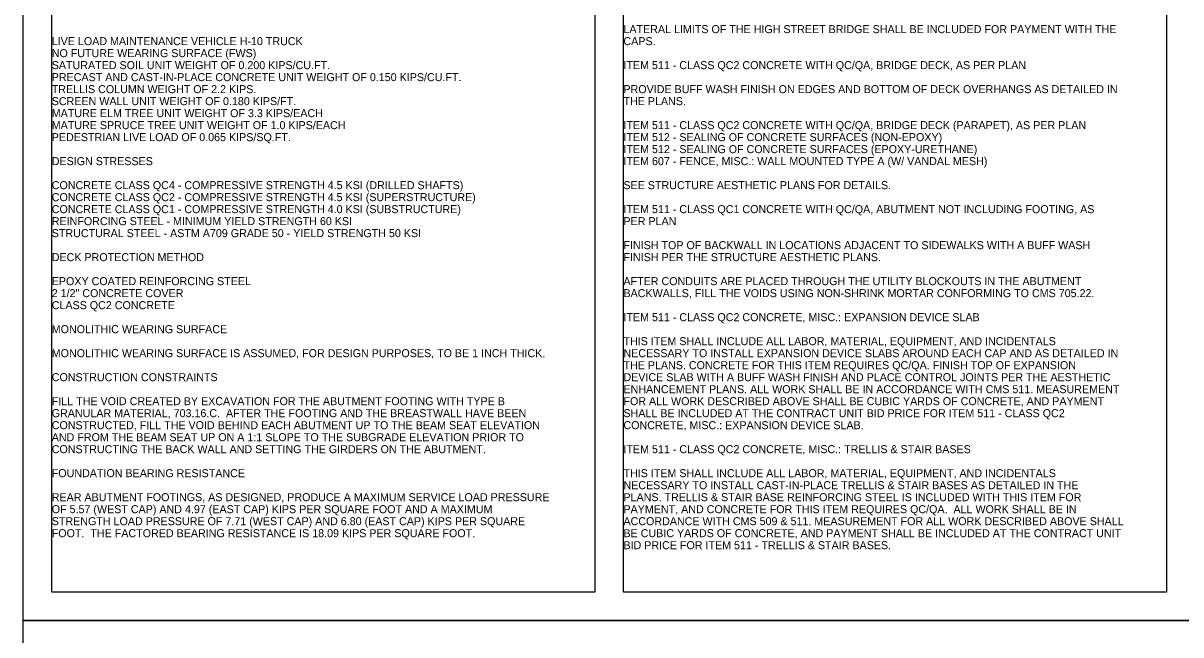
# Model space of a CAD drawing. Extents: x -27.4 to 41.5, y -43.2 to 24.4.
# Drawn here: x 1.24 to 21.49, y -1.99 to 8.71 of the extents above; entities that cross this region are included whole.
import ezdxf

# ---------------------------------------------------------------- set-up
doc = ezdxf.new("R2010")
doc.units = 0
for name, color, linetype in [('BR_P_Slab_Object', 7, 'Continuous'), ('BR_P_Sub_Foot_Hidden', 7, 'Continuous'), ('SH_Data', 7, 'Continuous')]:
    doc.layers.add(name, color=color, linetype=linetype)

msp = doc.modelspace()

# ---------------------------------------------------------------- linework, layer by layer
at = {"layer": 'BR_P_Slab_Object'}
for points in [[(1.744, 18.759), (11.244, 18.759), (11.244, -1.241), (1.744, -1.241)], [(11.744, 18.759), (21.244, 18.759), (21.244, -1.241), (11.744, -1.241)]]:
    msp.add_lwpolyline(points, close=True, dxfattribs=at)
at = {"layer": 'SH_Data'}
for points in [[(1.244, 19.259), (31.744, 19.259), (31.744, -1.741), (1.244, -1.741)], [(1.244, -1.741), (31.744, -1.741), (31.744, -22.741), (1.244, -22.741)]]:
    msp.add_lwpolyline(points, close=True, dxfattribs=at)

# ---------------------------------------------------------------- texts
at = {"layer": 'BR_P_Sub_Foot_Hidden'}
for s, p in [('LATERAL LIMITS OF THE HIGH STREET BRIDGE SHALL BE INCLUDED FOR PAYMENT WITH THE ', (11.744, 8.539)), ('LIVE LOAD MAINTENANCE VEHICLE H-10 TRUCK', (1.744, 8.329)), ('CAPS.', (11.744, 8.329)), ('NO FUTURE WEARING SURFACE (FWS) ', (1.744, 8.119)), ('SATURATED SOIL UNIT WEIGHT OF 0.200 KIPS/CU.FT.', (1.744, 7.909)), ('ITEM 511 - CLASS QC2 CONCRETE WITH QC/QA, BRIDGE DECK, AS PER PLAN', (11.744, 7.909)), ('ITEM 511 - CLASS QC2 CONCRETE WITH QC/QA, BRIDGE DECK, AS PER PLAN', (11.744, 7.909)), ('PRECAST AND CAST-IN-PLACE CONCRETE UNIT WEIGHT OF 0.150 KIPS/CU.FT.', (1.744, 7.699)), ('TRELLIS COLUMN WEIGHT OF 2.2 KIPS.', (1.744, 7.489)), ('PROVIDE BUFF WASH FINISH ON EDGES AND BOTTOM OF DECK OVERHANGS AS DETAILED IN ', (11.744, 7.489)), ('SCREEN WALL UNIT WEIGHT OF 0.180 KIPS/FT.', (1.744, 7.279)), ('THE PLANS.', (11.744, 7.279)), ('MATURE ELM TREE UNIT WEIGHT OF 3.3 KIPS/EACH', (1.744, 7.069)), ('MATURE SPRUCE TREE UNIT WEIGHT OF 1.0 KIPS/EACH', (1.744, 6.859)), ('ITEM 511 - CLASS QC2 CONCRETE WITH QC/QA, BRIDGE DECK (PARAPET), AS PER PLAN', (11.744, 6.859)), ('ITEM 511 - CLASS QC2 CONCRETE WITH QC/QA, BRIDGE DECK (PARAPET), AS PER PLAN', (11.744, 6.859)), ('PEDESTRIAN LIVE LOAD OF 0.065 KIPS/SQ.FT.', (1.744, 6.649)), ('ITEM 512 - SEALING OF CONCRETE SURFACES (NON-EPOXY)', (11.744, 6.649)), ('ITEM 512 - SEALING OF CONCRETE SURFACES (NON-EPOXY)', (11.744, 6.649)), ('ITEM 512 - SEALING OF CONCRETE SURFACES (EPOXY-URETHANE)', (11.744, 6.439)), ('ITEM 512 - SEALING OF CONCRETE SURFACES (EPOXY-URETHANE)', (11.744, 6.439)), ('DESIGN STRESSES', (1.744, 6.229)), ('DESIGN STRESSES', (1.744, 6.229)), ('ITEM 607 - FENCE, MISC.: WALL MOUNTED TYPE A (W/ VANDAL MESH)', (11.744, 6.229)), ('ITEM 607 - FENCE, MISC.: WALL MOUNTED TYPE A (W/ VANDAL MESH)', (11.744, 6.229)), ('CONCRETE CLASS QC4 - COMPRESSIVE STRENGTH 4.5 KSI (DRILLED SHAFTS)', (1.744, 5.809)), ('SEE STRUCTURE AESTHETIC PLANS FOR DETAILS.', (11.744, 5.809)), ('CONCRETE CLASS QC2 - COMPRESSIVE STRENGTH 4.5 KSI (SUPERSTRUCTURE)', (1.744, 5.599)), ('CONCRETE CLASS QC1 - COMPRESSIVE STRENGTH 4.0 KSI (SUBSTRUCTURE)                                  ', (1.744, 5.389)), ('ITEM 511 - CLASS QC1 CONCRETE WITH QC/QA, ABUTMENT NOT INCLUDING FOOTING, AS ', (11.744, 5.389)), ('ITEM 511 - CLASS QC1 CONCRETE WITH QC/QA, ABUTMENT NOT INCLUDING FOOTING, AS ', (11.744, 5.389)), ('REINFORCING STEEL - MINIMUM YIELD STRENGTH 60 KSI', (1.744, 5.179)), ('PER PLAN', (11.744, 5.179)), ('PER PLAN', (11.744, 5.179)), ('STRUCTURAL STEEL - ASTM A709 GRADE 50 - YIELD STRENGTH 50 KSI', (1.744, 4.969)), ('FINISH TOP OF BACKWALL IN LOCATIONS ADJACENT TO SIDEWALKS WITH A BUFF WASH ', (11.744, 4.759)), ('DECK PROTECTION METHOD', (1.744, 4.549)), ('DECK PROTECTION METHOD', (1.744, 4.549)), ('FINISH PER THE STRUCTURE AESTHETIC PLANS. ', (11.744, 4.549)), ('EPOXY COATED REINFORCING STEEL', (1.744, 4.129)), ('AFTER CONDUITS ARE PLACED THROUGH THE UTILITY BLOCKOUTS IN THE ABUTMENT ', (11.744, 4.129)), ('2 1/2" CONCRETE COVER', (1.744, 3.919)), ('BACKWALLS, FILL THE VOIDS USING NON-SHRINK MORTAR CONFORMING TO CMS 705.22. ', (11.744, 3.919)), ('CLASS QC2 CONCRETE', (1.744, 3.709)), ('ITEM 511 - CLASS QC2 CONCRETE, MISC.: EXPANSION DEVICE SLAB', (11.744, 3.499)), ('ITEM 511 - CLASS QC2 CONCRETE, MISC.: EXPANSION DEVICE SLAB', (11.744, 3.499)), ('MONOLITHIC WEARING SURFACE', (1.744, 3.289)), ('MONOLITHIC WEARING SURFACE', (1.744, 3.289)), ('THIS ITEM SHALL INCLUDE ALL LABOR, MATERIAL, EQUIPMENT, AND INCIDENTALS ', (11.744, 3.079)), ('MONOLITHIC WEARING SURFACE IS ASSUMED, FOR DESIGN PURPOSES, TO BE 1 INCH THICK.', (1.744, 2.869)), ('NECESSARY TO INSTALL EXPANSION DEVICE SLABS AROUND EACH CAP AND AS DETAILED IN ', (11.744, 2.869)), ('THE PLANS. CONCRETE FOR THIS ITEM REQUIRES QC/QA. FINISH TOP OF EXPANSION ', (11.744, 2.659)), ('CONSTRUCTION CONSTRAINTS', (1.744, 2.449)), ('CONSTRUCTION CONSTRAINTS', (1.744, 2.449)), ('DEVICE SLAB WITH A BUFF WASH FINISH AND PLACE CONTROL JOINTS PER THE AESTHETIC ', (11.744, 2.449)), ('ENHANCEMENT PLANS. ALL WORK SHALL BE IN ACCORDANCE WITH CMS 511. MEASUREMENT ', (11.744, 2.239)), ('FILL THE VOID CREATED BY EXCAVATION FOR THE ABUTMENT FOOTING WITH TYPE B ', (1.744, 2.029)), ('FOR ALL WORK DESCRIBED ABOVE SHALL BE CUBIC YARDS OF CONCRETE, AND PAYMENT ', (11.744, 2.029)), ('GRANULAR MATERIAL, 703.16.C.  AFTER THE FOOTING AND THE BREASTWALL HAVE BEEN ', (1.744, 1.819)), ('SHALL BE INCLUDED AT THE CONTRACT UNIT BID PRICE FOR ITEM 511 - CLASS QC2 ', (11.744, 1.819)), ('CONSTRUCTED, FILL THE VOID BEHIND EACH ABUTMENT UP TO THE BEAM SEAT ELEVATION ', (1.744, 1.609)), ('CONCRETE, MISC.: EXPANSION DEVICE SLAB.', (11.744, 1.609)), ('AND FROM THE BEAM SEAT UP ON A 1:1 SLOPE TO THE SUBGRADE ELEVATION PRIOR TO ', (1.744, 1.399)), ('CONSTRUCTING THE BACK WALL AND SETTING THE GIRDERS ON THE ABUTMENT.', (1.744, 1.189)), ('ITEM 511 - CLASS QC2 CONCRETE, MISC.: TRELLIS & STAIR BASES', (11.744, 1.189)), ('ITEM 511 - CLASS QC2 CONCRETE, MISC.: TRELLIS & STAIR BASES', (11.744, 1.189)), ('FOUNDATION BEARING RESISTANCE', (1.744, 0.769)), ('FOUNDATION BEARING RESISTANCE', (1.744, 0.769)), ('THIS ITEM SHALL INCLUDE ALL LABOR, MATERIAL, EQUIPMENT, AND INCIDENTALS ', (11.744, 0.769)), ('NECESSARY TO INSTALL CAST-IN-PLACE TRELLIS & STAIR BASES AS DETAILED IN THE ', (11.744, 0.559)), ('REAR ABUTMENT FOOTINGS, AS DESIGNED, PRODUCE A MAXIMUM SERVICE LOAD PRESSURE ', (1.744, 0.349)), ('PLANS. TRELLIS & STAIR BASE REINFORCING STEEL IS INCLUDED WITH THIS ITEM FOR ', (11.744, 0.349)), ('OF 5.57 (WEST CAP) AND 4.97 (EAST CAP) KIPS PER SQUARE FOOT AND A MAXIMUM ', (1.744, 0.139)), ('PAYMENT, AND CONCRETE FOR THIS ITEM REQUIRES QC/QA.  ALL WORK SHALL BE IN ', (11.744, 0.139)), ('STRENGTH LOAD PRESSURE OF 7.71 (WEST CAP) AND 6.80 (EAST CAP) KIPS PER SQUARE ', (1.744, -0.071)), ('ACCORDANCE WITH CMS 509 & 511. MEASUREMENT FOR ALL WORK DESCRIBED ABOVE SHALL ', (11.744, -0.071)), ('FOOT.  THE FACTORED BEARING RESISTANCE IS 18.09 KIPS PER SQUARE FOOT.', (1.744, -0.281)), ('BE CUBIC YARDS OF CONCRETE, AND PAYMENT SHALL BE INCLUDED AT THE CONTRACT UNIT ', (11.744, -0.281)), ('BID PRICE FOR ITEM 511 - TRELLIS & STAIR BASES.', (11.744, -0.491))]:
    msp.add_text(s, height=0.14, dxfattribs=at).set_placement(p)

doc.saveas('drawing.dxf')
